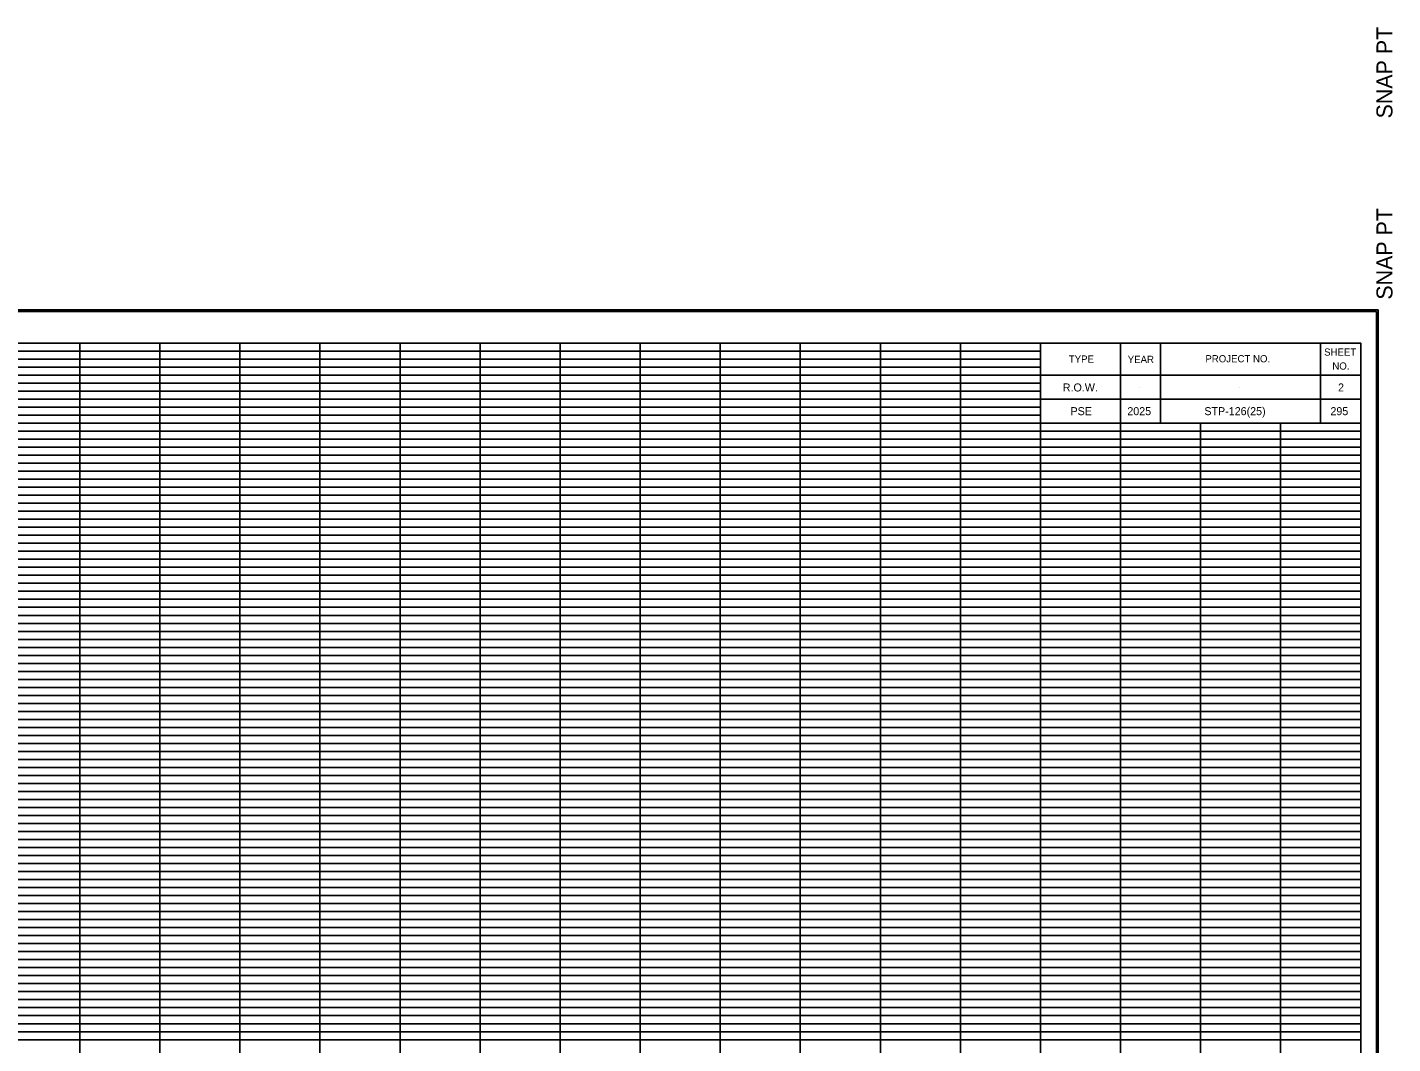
# Model space of a CAD drawing. Extents: x 980 to 2064, y 978 to 2267.
# Drawn here: x 1153.4 to 1324, y 1382.5 to 1509.4 of the extents above; entities that cross this region are included whole.
import ezdxf

# ---------------------------------------------------------------- set-up
doc = ezdxf.new("R2010")
doc.units = 0
for name, color, linetype in [('Default', 7, 'Continuous'), ('DESIGN - SCRATCH - User 1', 7, 'Continuous'), ('DESIGN - SHEET - Corner Text', 7, 'Continuous'), ('DESIGN - SHEET - Light Grid', 7, 'Continuous'), ('DESIGN - SHEET - Linework', 7, 'Continuous'), ('DESIGN - SHEET - Plot Shape', 7, 'Continuous')]:
    doc.layers.add(name, color=color, linetype=linetype)

# ---------------------------------------------------------------- blocks, each defined once
blk = doc.blocks.new('XSTSHT')
at = {"layer": 'DESIGN - SHEET - Corner Text'}
blk.add_text('SNAP PT  ', height=0.2, rotation=90, dxfattribs=at).set_placement((32.397, -2.194))

msp = doc.modelspace()

# ---------------------------------------------------------------- linework, layer by layer
at = {"layer": 'DESIGN - SCRATCH - User 1'}
for p, q in [((1285, 1464.5), (1285, 1464.5)), ((1292.4, 1464.5), (1292.4, 1464.5)), ((1304.9, 1464.5), (1304.9, 1464.5)), ((1317.4, 1464.5), (1317.4, 1464.5)), ((1285, 1461.5), (1285, 1461.5)), ((1292.4, 1461.5), (1292.4, 1461.5)), ((1304.9, 1461.5), (1304.9, 1461.5)), ((1317.4, 1461.5), (1317.4, 1461.5))]:
    msp.add_line(p, q, dxfattribs=at)
at = {"layer": 'DESIGN - SHEET - Light Grid'}
for p, q in [((1080, 1469), (1160, 1469)), ((1160, 1469), (1240, 1469)), ((1240, 1469), (1280, 1469)), ((1080, 1468), (1160, 1468)), ((1080, 1467), (1160, 1467)), ((1160, 1468), (1240, 1468)), ((1160, 1467), (1240, 1467)), ((1240, 1468), (1280, 1468)), ((1240, 1467), (1280, 1467)), ((1080, 1466), (1160, 1466)), ((1160, 1466), (1240, 1466)), ((1240, 1466), (1280, 1466)), ((1080, 1465), (1160, 1465)), ((1080, 1464), (1160, 1464)), ((1160, 1465), (1240, 1465)), ((1160, 1464), (1240, 1464)), ((1240, 1465), (1280, 1465)), ((1240, 1464), (1280, 1464)), ((1080, 1463), (1160, 1463)), ((1080, 1462), (1160, 1462)), ((1160, 1463), (1240, 1463)), ((1160, 1462), (1240, 1462)), ((1240, 1463), (1280, 1463)), ((1240, 1462), (1280, 1462)), ((1080, 1461), (1160, 1461)), ((1160, 1461), (1240, 1461)), ((1240, 1461), (1280, 1461)), ((1080, 1459), (1160, 1459)), ((1160, 1459), (1240, 1459)), ((1240, 1459), (1320, 1459)), ((1080, 1458), (1160, 1458)), ((1080, 1457), (1160, 1457)), ((1160, 1458), (1240, 1458)), ((1160, 1457), (1240, 1457)), ((1240, 1458), (1320, 1458)), ((1240, 1457), (1320, 1457)), ((1080, 1456), (1160, 1456)), ((1080, 1455), (1160, 1455)), ((1160, 1456), (1240, 1456)), ((1160, 1455), (1240, 1455)), ((1240, 1456), (1320, 1456)), ((1240, 1455), (1320, 1455)), ((1080, 1454), (1160, 1454)), ((1160, 1454), (1240, 1454)), ((1240, 1454), (1320, 1454)), ((1080, 1453), (1160, 1453)), ((1080, 1452), (1160, 1452)), ((1160, 1453), (1240, 1453)), ((1160, 1452), (1240, 1452)), ((1240, 1453), (1320, 1453)), ((1240, 1452), (1320, 1452)), ((1080, 1451), (1160, 1451)), ((1160, 1451), (1240, 1451)), ((1240, 1451), (1320, 1451)), ((1080, 1449), (1160, 1449)), ((1160, 1449), (1240, 1449)), ((1240, 1449), (1320, 1449)), ((1080, 1448), (1160, 1448)), ((1080, 1447), (1160, 1447)), ((1160, 1448), (1240, 1448)), ((1160, 1447), (1240, 1447)), ((1240, 1448), (1320, 1448)), ((1240, 1447), (1320, 1447)), ((1080, 1446), (1160, 1446)), ((1080, 1445), (1160, 1445)), ((1160, 1446), (1240, 1446)), ((1160, 1445), (1240, 1445)), ((1240, 1446), (1320, 1446)), ((1240, 1445), (1320, 1445)), ((1080, 1444), (1160, 1444)), ((1080, 1443), (1160, 1443)), ((1160, 1444), (1240, 1444)), ((1160, 1443), (1240, 1443)), ((1240, 1444), (1320, 1444)), ((1240, 1443), (1320, 1443)), ((1080, 1442), (1160, 1442)), ((1160, 1442), (1240, 1442)), ((1240, 1442), (1320, 1442)), ((1080, 1441), (1160, 1441)), ((1160, 1441), (1240, 1441)), ((1240, 1441), (1320, 1441)), ((1080, 1439), (1160, 1439)), ((1080, 1438), (1160, 1438)), ((1160, 1439), (1240, 1439)), ((1160, 1438), (1240, 1438)), ((1240, 1439), (1320, 1439)), ((1240, 1438), (1320, 1438)), ((1080, 1437), (1160, 1437)), ((1160, 1437), (1240, 1437)), ((1240, 1437), (1320, 1437)), ((1080, 1436), (1160, 1436)), ((1080, 1435), (1160, 1435)), ((1160, 1436), (1240, 1436)), ((1160, 1435), (1240, 1435)), ((1240, 1436), (1320, 1436)), ((1240, 1435), (1320, 1435)), ((1080, 1434), (1160, 1434)), ((1080, 1433), (1160, 1433)), ((1160, 1434), (1240, 1434)), ((1160, 1433), (1240, 1433)), ((1240, 1434), (1320, 1434)), ((1240, 1433), (1320, 1433)), ((1080, 1432), (1160, 1432)), ((1080, 1431), (1160, 1431)), ((1160, 1432), (1240, 1432)), ((1160, 1431), (1240, 1431)), ((1240, 1432), (1320, 1432)), ((1240, 1431), (1320, 1431)), ((1080, 1429), (1160, 1429)), ((1080, 1428), (1160, 1428)), ((1160, 1429), (1240, 1429)), ((1160, 1428), (1240, 1428)), ((1240, 1429), (1320, 1429)), ((1240, 1428), (1320, 1428)), ((1080, 1427), (1160, 1427)), ((1080, 1426), (1160, 1426)), ((1160, 1427), (1240, 1427)), ((1160, 1426), (1240, 1426)), ((1240, 1427), (1320, 1427)), ((1240, 1426), (1320, 1426)), ((1080, 1425), (1160, 1425)), ((1160, 1425), (1240, 1425)), ((1240, 1425), (1320, 1425)), ((1080, 1424), (1160, 1424)), ((1080, 1423), (1160, 1423)), ((1160, 1424), (1240, 1424)), ((1160, 1423), (1240, 1423)), ((1240, 1424), (1320, 1424)), ((1240, 1423), (1320, 1423)), ((1080, 1422), (1160, 1422)), ((1080, 1421), (1160, 1421)), ((1160, 1422), (1240, 1422)), ((1160, 1421), (1240, 1421)), ((1240, 1422), (1320, 1422)), ((1240, 1421), (1320, 1421)), ((1080, 1419), (1160, 1419)), ((1080, 1418), (1160, 1418)), ((1160, 1419), (1240, 1419)), ((1160, 1418), (1240, 1418)), ((1240, 1419), (1320, 1419)), ((1240, 1418), (1320, 1418)), ((1080, 1417), (1160, 1417)), ((1080, 1416), (1160, 1416)), ((1160, 1417), (1240, 1417)), ((1160, 1416), (1240, 1416)), ((1240, 1417), (1320, 1417)), ((1240, 1416), (1320, 1416)), ((1080, 1415), (1160, 1415)), ((1080, 1414), (1160, 1414)), ((1160, 1415), (1240, 1415)), ((1160, 1414), (1240, 1414)), ((1240, 1415), (1320, 1415)), ((1240, 1414), (1320, 1414)), ((1080, 1413), (1160, 1413)), ((1160, 1413), (1240, 1413)), ((1240, 1413), (1320, 1413)), ((1080, 1412), (1160, 1412)), ((1080, 1411), (1160, 1411)), ((1160, 1412), (1240, 1412)), ((1160, 1411), (1240, 1411)), ((1240, 1412), (1320, 1412)), ((1240, 1411), (1320, 1411)), ((1080, 1409), (1160, 1409)), ((1160, 1409), (1240, 1409)), ((1240, 1409), (1320, 1409)), ((1080, 1408), (1160, 1408)), ((1160, 1408), (1240, 1408)), ((1240, 1408), (1320, 1408)), ((1080, 1407), (1160, 1407)), ((1080, 1406), (1160, 1406)), ((1160, 1407), (1240, 1407)), ((1160, 1406), (1240, 1406)), ((1240, 1407), (1320, 1407)), ((1240, 1406), (1320, 1406)), ((1080, 1405), (1160, 1405)), ((1080, 1404), (1160, 1404)), ((1160, 1405), (1240, 1405)), ((1160, 1404), (1240, 1404)), ((1240, 1405), (1320, 1405)), ((1240, 1404), (1320, 1404)), ((1080, 1403), (1160, 1403)), ((1080, 1402), (1160, 1402)), ((1160, 1403), (1240, 1403)), ((1160, 1402), (1240, 1402)), ((1240, 1403), (1320, 1403)), ((1240, 1402), (1320, 1402)), ((1080, 1401), (1160, 1401)), ((1160, 1401), (1240, 1401)), ((1240, 1401), (1320, 1401)), ((1080, 1399), (1160, 1399)), ((1160, 1399), (1240, 1399)), ((1240, 1399), (1320, 1399)), ((1080, 1398), (1160, 1398)), ((1080, 1397), (1160, 1397)), ((1160, 1398), (1240, 1398)), ((1160, 1397), (1240, 1397)), ((1240, 1398), (1320, 1398)), ((1240, 1397), (1320, 1397)), ((1080, 1396), (1160, 1396)), ((1160, 1396), (1240, 1396)), ((1240, 1396), (1320, 1396)), ((1080, 1395), (1160, 1395)), ((1080, 1394), (1160, 1394)), ((1160, 1395), (1240, 1395)), ((1160, 1394), (1240, 1394)), ((1240, 1395), (1320, 1395)), ((1240, 1394), (1320, 1394)), ((1080, 1393), (1160, 1393)), ((1080, 1392), (1160, 1392)), ((1160, 1393), (1240, 1393)), ((1160, 1392), (1240, 1392)), ((1240, 1393), (1320, 1393)), ((1240, 1392), (1320, 1392)), ((1080, 1391), (1160, 1391)), ((1160, 1391), (1240, 1391)), ((1240, 1391), (1320, 1391)), ((1080, 1389), (1160, 1389)), ((1160, 1389), (1240, 1389)), ((1240, 1389), (1320, 1389)), ((1080, 1388), (1160, 1388)), ((1080, 1387), (1160, 1387)), ((1160, 1388), (1240, 1388)), ((1160, 1387), (1240, 1387)), ((1240, 1388), (1320, 1388)), ((1240, 1387), (1320, 1387)), ((1080, 1386), (1160, 1386)), ((1080, 1385), (1160, 1385)), ((1160, 1386), (1240, 1386)), ((1160, 1385), (1240, 1385)), ((1240, 1386), (1320, 1386)), ((1240, 1385), (1320, 1385)), ((1080, 1384), (1160, 1384)), ((1160, 1384), (1240, 1384)), ((1240, 1384), (1320, 1384)), ((1080, 1383), (1160, 1383)), ((1160, 1383), (1240, 1383)), ((1240, 1383), (1320, 1383))]:
    msp.add_line(p, q, dxfattribs=at)
at = {"layer": 'DESIGN - SHEET - Linework'}
for p, q in [((981.77, 1474.14), (1322.17, 1474.14)), ((1322.17, 1474.14), (1322.17, 1255.86)), ((1160, 1260), (1160, 1470)), ((1170, 1260), (1170, 1470)), ((1180, 1260), (1180, 1470)), ((1190, 1260), (1190, 1470)), ((1200, 1260), (1200, 1470)), ((1210, 1260), (1210, 1470)), ((1220, 1260), (1220, 1470)), ((1230, 1260), (1230, 1470)), ((1240, 1260), (1240, 1470)), ((1250, 1260), (1250, 1470)), ((1260, 1260), (1260, 1470)), ((1270, 1260), (1270, 1470)), ((1000, 1460), (1280, 1460)), ((1280, 1260), (1280, 1460)), ((1290, 1260), (1290, 1460)), ((1300, 1260), (1300, 1460)), ((1310, 1260), (1310, 1460)), ((1000, 1450), (1320, 1450)), ((1000, 1440), (1320, 1440)), ((1000, 1430), (1320, 1430)), ((1000, 1420), (1320, 1420)), ((1000, 1410), (1320, 1410)), ((1000, 1400), (1320, 1400)), ((1000, 1390), (1320, 1390))]:
    msp.add_line(p, q, dxfattribs=at)
for points in [[(1000, 1470), (1000, 1260), (1320, 1260), (1320, 1470), (1000, 1470)], [(1280, 1470), (1280, 1460), (1320, 1460), (1320, 1470), (1315, 1470), (1315, 1460), (1295, 1460), (1295, 1470), (1290, 1470), (1290, 1460), (1320, 1460), (1280, 1460), (1280, 1463), (1320, 1463), (1320, 1466), (1280, 1466)]]:
    msp.add_lwpolyline(points, dxfattribs=at)
at = {"layer": 'DESIGN - SHEET - Plot Shape'}
for points in [[(981.97, 1473.94), (1321.97, 1473.94), (1321.97, 1256.06), (981.97, 1256.06)], [(991.5, 1470), (1320, 1470), (1320, 1257.5), (991.5, 1257.5)]]:
    msp.add_lwpolyline(points, close=True, dxfattribs=at)

# ---------------------------------------------------------------- block references
at = {"layer": 'Default', "xscale": 10, "yscale": 10}
msp.add_blockref('XSTSHT', (1000, 1520), dxfattribs=at)

# ---------------------------------------------------------------- texts
at = {"layer": 'DESIGN - SHEET - Corner Text'}
msp.add_text('  SNAP PT', height=2, rotation=90, dxfattribs=at).set_placement((1323.97, 1473.94))
for s, height, p in [('PROJECT NO.', 0.9, (1300.6, 1467.6)), ('SHEET', 0.9, (1315.43, 1468.43)), ('TYPE', 0.9, (1283.54, 1467.56)), ('YEAR', 0.9, (1290.9, 1467.52)), ('NO.', 0.9, (1316.46, 1466.69)), ('R.O.W.', 1, (1282.79, 1463.96)), ('2', 1, (1317.17, 1463.96)), ('PSE', 1, (1283.75, 1461)), ('2025', 1, (1290.85, 1461)), ('STP-126(25)', 1, (1300.47, 1461)), ('295', 1, (1316.22, 1461))]:
    msp.add_text(s, height=height, dxfattribs=at).set_placement(p)

doc.saveas('drawing.dxf')
